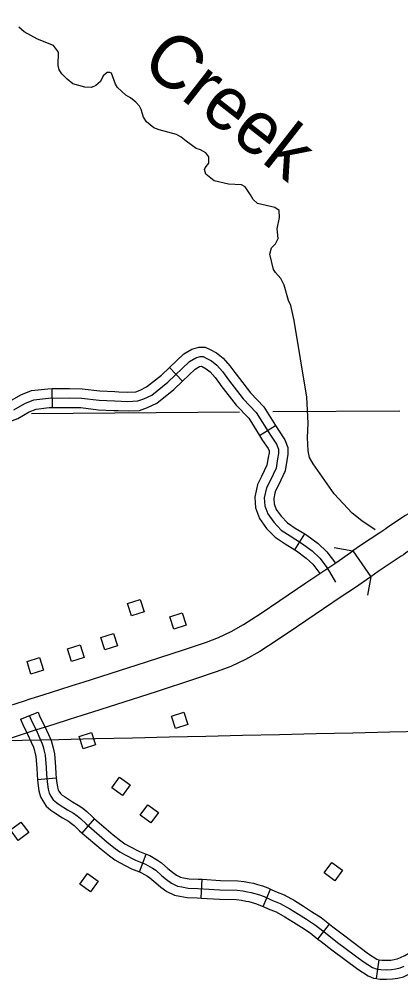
# Model space of a CAD drawing. Extents: x -19 to 366, y -4 to 359.
# Drawn here: x 128.531 to 129.107, y 199.218 to 200.67 of the extents above; entities that cross this region are included whole.
import ezdxf

# ---------------------------------------------------------------- set-up
doc = ezdxf.new("R2010")
doc.units = 0
for name, color, linetype in [('Level 10', 7, 'Continuous'), ('Level 32', 7, 'Continuous'), ('Level 35', 7, 'Continuous'), ('Level 37', 7, 'Continuous'), ('Level 45', 7, 'Continuous'), ('Level 5', 7, 'Continuous'), ('Level 56', 7, 'Continuous'), ('Level 60', 7, 'Continuous')]:
    doc.layers.add(name, color=color, linetype=linetype)

msp = doc.modelspace()

# ---------------------------------------------------------------- linework, layer by layer
at = {"layer": 'Level 10'}
msp.add_line((129.0347, 199.8689), (129.0618, 199.8301), dxfattribs=at)
for points in [[(129.1175, 199.9246), (129.1141, 199.9223), (129.0877, 199.9047), (129.0845, 199.9025), (129.0814, 199.9005), (129.0784, 199.8984), (129.0753, 199.8963), (129.0463, 199.8771), (129.0347, 199.8689)], [(129.1442, 199.8855), (129.1405, 199.883), (129.1141, 199.8654), (129.111, 199.8633), (129.1078, 199.8612), (129.1046, 199.859), (129.1015, 199.8569), (129.073, 199.8379), (129.0618, 199.8301)], [(128.5393, 199.6433), (128.548, 199.6461), (128.569, 199.6526), (128.5924, 199.6601), (128.6113, 199.6662), (128.6278, 199.6714), (128.7236, 199.702), (128.7808, 199.7206), (128.8139, 199.7317), (128.8319, 199.7386), (128.8509, 199.7474), (128.8695, 199.7581), (128.8949, 199.7743), (128.9247, 199.7942), (128.9639, 199.8209), (128.9909, 199.8389), (129.0103, 199.8519), (129.0347, 199.8689)], [(129.0618, 199.8301), (129.037, 199.8128), (129.0172, 199.7996), (128.9904, 199.7816), (128.9512, 199.7549), (128.9207, 199.7346), (128.8941, 199.7177), (128.8728, 199.7053), (128.8504, 199.695), (128.8299, 199.6871), (128.7956, 199.6756), (128.7381, 199.6569), (128.642, 199.6262), (128.6256, 199.6211), (128.6069, 199.6151), (128.5833, 199.6075), (128.5623, 199.6009), (128.554, 199.5982)], [(128.5046, 199.6319), (128.5393, 199.6433)], [(128.554, 199.5982), (128.5192, 199.5869)]]:
    msp.add_lwpolyline(points, dxfattribs=at)
at = {"layer": 'Level 32'}
for p, q in [((128.5334, 199.6156), (128.5599, 199.6259)), ((128.5588, 199.5244), (128.5871, 199.5269)), ((128.6265, 199.444), (128.6451, 199.4655)), ((128.7126, 199.3854), (128.7228, 199.412)), ((128.8058, 199.3459), (128.8074, 199.3743)), ((128.8993, 199.3333), (128.9105, 199.3594)), ((128.982, 199.2843), (128.9993, 199.3069)), ((129.0704, 199.2248), (129.0744, 199.2529))]:
    msp.add_line(p, q, dxfattribs=at)
for points in [[(128.5466, 199.6207), (128.5496, 199.6132), (128.5567, 199.5993), (128.5625, 199.5865), (128.566, 199.5783), (128.5675, 199.5738), (128.5687, 199.5691), (128.5704, 199.5613), (128.5721, 199.5427), (128.5724, 199.5324), (128.5734, 199.5209), (128.575, 199.5103), (128.5767, 199.5038), (128.579, 199.4996), (128.5827, 199.494), (128.5876, 199.4898), (128.5915, 199.4871), (128.6041, 199.479), (128.6131, 199.4737), (128.6188, 199.47), (128.6238, 199.4659), (128.6321, 199.4579), (128.6639, 199.4304), (128.6759, 199.4208), (128.683, 199.4158), (128.6904, 199.4116), (128.7067, 199.4029), (128.7221, 199.397), (128.7323, 199.3911), (128.7372, 199.3878), (128.7465, 199.3797), (128.7536, 199.3738), (128.7612, 199.3682), (128.7703, 199.3641), (128.7765, 199.3627), (128.7861, 199.3611), (128.8006, 199.3604), (128.8342, 199.3585), (128.8603, 199.3578), (128.8685, 199.3567), (128.8758, 199.3555), (128.8814, 199.3545), (128.8869, 199.3528), (128.8936, 199.3509), (128.9009, 199.3481), (128.9125, 199.343), (128.9251, 199.3379), (128.9394, 199.33), (128.9527, 199.3216), (128.9648, 199.314), (128.9784, 199.305), (128.9958, 199.2916), (129.0117, 199.2792), (129.0504, 199.2504), (129.0644, 199.2415), (129.0697, 199.2392), (129.0771, 199.2382), (129.0854, 199.2381), (129.0932, 199.2383), (129.0997, 199.2392), (129.1063, 199.2408), (129.1123, 199.2436)], [(128.5599, 199.6259), (128.5625, 199.619), (128.5695, 199.6055), (128.5755, 199.5922), (128.5793, 199.5833), (128.5811, 199.5777), (128.5825, 199.5724), (128.5845, 199.5635), (128.5863, 199.5435), (128.5866, 199.5332), (128.5871, 199.5269)], [(128.5334, 199.6156), (128.5366, 199.6074), (128.5439, 199.5931), (128.5495, 199.5807), (128.5527, 199.5733), (128.5538, 199.5699), (128.5549, 199.5657), (128.5564, 199.5591), (128.5579, 199.5418), (128.5582, 199.5315), (128.5588, 199.5244)], [(128.5588, 199.5244), (128.5593, 199.5192), (128.5611, 199.5074), (128.5634, 199.4986), (128.5668, 199.4923), (128.5719, 199.4845), (128.5789, 199.4786), (128.5836, 199.4753), (128.5967, 199.4669), (128.6056, 199.4616), (128.6104, 199.4585), (128.6143, 199.4553), (128.6225, 199.4474), (128.6265, 199.444)], [(128.5871, 199.5269), (128.5875, 199.5226), (128.589, 199.5132), (128.59, 199.5091), (128.5912, 199.5068), (128.5934, 199.5035), (128.5962, 199.5011), (128.5994, 199.4989), (128.6116, 199.4911), (128.6205, 199.4858), (128.6272, 199.4815), (128.6332, 199.4765), (128.6417, 199.4684), (128.6451, 199.4655)], [(128.6451, 199.4655), (128.673, 199.4413), (128.6845, 199.4321), (128.6906, 199.4278), (128.6972, 199.4241), (128.7126, 199.4159), (128.7228, 199.412)], [(128.6265, 199.444), (128.6548, 199.4195), (128.6674, 199.4094), (128.6754, 199.4038), (128.6836, 199.3992), (128.7008, 199.39), (128.7126, 199.3854)], [(128.7228, 199.412), (128.7282, 199.4099), (128.7398, 199.4032), (128.7459, 199.3991), (128.7557, 199.3906), (128.7624, 199.385), (128.7685, 199.3805), (128.7749, 199.3776), (128.7792, 199.3766), (128.7876, 199.3752), (128.8013, 199.3746), (128.8074, 199.3743)], [(128.7126, 199.3854), (128.7159, 199.3842), (128.7247, 199.379), (128.7286, 199.3765), (128.7373, 199.3689), (128.7449, 199.3626), (128.754, 199.3559), (128.7657, 199.3506), (128.7737, 199.3487), (128.7847, 199.3469), (128.7999, 199.3463), (128.8058, 199.3459)], [(128.8074, 199.3743), (128.8349, 199.3727), (128.8614, 199.372), (128.8706, 199.3708), (128.8782, 199.3695), (128.8848, 199.3684), (128.8909, 199.3664), (128.8982, 199.3644), (128.9063, 199.3612), (128.9105, 199.3594)], [(128.9105, 199.3594), (128.918, 199.3561), (128.9312, 199.3507), (128.9467, 199.3422), (128.9603, 199.3336), (128.9725, 199.3259), (128.9867, 199.3166), (128.9993, 199.3069)], [(128.8058, 199.3459), (128.8336, 199.3443), (128.8592, 199.3436), (128.8665, 199.3427), (128.8734, 199.3415), (128.878, 199.3407), (128.8828, 199.3392), (128.8891, 199.3374), (128.8955, 199.3349), (128.8993, 199.3333)], [(128.8993, 199.3333), (128.907, 199.3299), (128.919, 199.3251), (128.9322, 199.3178), (128.9451, 199.3096), (128.9571, 199.302), (128.9702, 199.2934), (128.982, 199.2843)], [(128.9993, 199.3069), (129.0045, 199.3028), (129.0204, 199.2904), (129.0584, 199.2621), (129.071, 199.2541), (129.0736, 199.253), (129.0744, 199.2529)], [(128.982, 199.2843), (128.9871, 199.2804), (129.0031, 199.2679), (129.0423, 199.2387), (129.0577, 199.229), (129.0658, 199.2254), (129.0704, 199.2248)], [(129.0744, 199.2529), (129.0782, 199.2524), (129.0853, 199.2523), (129.092, 199.2525), (129.0971, 199.2532), (129.1016, 199.2543), (129.1064, 199.2565), (129.1131, 199.2596), (129.1225, 199.2648), (129.1361, 199.2758), (129.1441, 199.2828), (129.149, 199.2853), (129.154, 199.2874), (129.1569, 199.2885)], [(129.0704, 199.2248), (129.076, 199.224), (129.0856, 199.2239), (129.0944, 199.2241), (129.1024, 199.2252), (129.111, 199.2274), (129.1182, 199.2307), (129.1259, 199.2342), (129.1384, 199.2411), (129.1543, 199.254), (129.1602, 199.2591), (129.1611, 199.2596), (129.1645, 199.261), (129.1668, 199.2619)]]:
    msp.add_lwpolyline(points, dxfattribs=at)
at = {"layer": 'Level 35'}
for points in [[(128.931, 200.2695), (128.926, 200.2793), (128.9179, 200.2883), (128.9148, 200.2932), (128.9095, 200.3162), (128.912, 200.3254), (128.918, 200.3319), (128.922, 200.3399), (128.9207, 200.3543), (128.9242, 200.3714), (128.9233, 200.3817), (128.9168, 200.3865), (128.8909, 200.3922), (128.8844, 200.3986), (128.8805, 200.4057), (128.8724, 200.4174), (128.8667, 200.4203), (128.8469, 200.4216), (128.8257, 200.4266), (128.8127, 200.4366), (128.811, 200.4435), (128.8117, 200.4461), (128.8173, 200.453), (128.8172, 200.4625), (128.8129, 200.4689), (128.8049, 200.4733), (128.7984, 200.4751), (128.7831, 200.4863), (128.7758, 200.4923), (128.7686, 200.4963), (128.7424, 200.5032), (128.7344, 200.5065), (128.7233, 200.5154), (128.7186, 200.5226), (128.7154, 200.5339), (128.7127, 200.5392), (128.7073, 200.5452), (128.6992, 200.5515), (128.692, 200.5556), (128.6797, 200.5672), (128.6766, 200.5721), (128.6707, 200.5887), (128.668, 200.5898), (128.6642, 200.5897), (128.6582, 200.5847), (128.6538, 200.5763), (128.6467, 200.5701), (128.6403, 200.5674), (128.6301, 200.5676), (128.6122, 200.5727), (128.6038, 200.5798), (128.5957, 200.5876), (128.5915, 200.594), (128.5899, 200.6001), (128.5907, 200.6202), (128.583, 200.6307), (128.559, 200.6398), (128.5387, 200.6513), (128.5307, 200.658)], [(129.0682, 199.9009), (129.0481, 199.9145), (129.0339, 199.9261), (129.0066, 199.9549), (128.9749, 200), (128.9691, 200.0098), (128.9674, 200.0196), (128.9663, 200.0397), (128.9671, 200.0617), (128.9654, 200.1004), (128.9462, 200.2162), (128.941, 200.2389), (128.9374, 200.2464), (128.931, 200.2695)]]:
    msp.add_lwpolyline(points, dxfattribs=at)
at = {"layer": 'Level 37'}
for points in [[(129.0067, 199.8739), (129.0347, 199.8689)], [(129.0618, 199.8301), (129.0568, 199.8022)]]:
    msp.add_lwpolyline(points, dxfattribs=at)
at = {"layer": 'Level 45'}
for p, q in [((128.7776, 200.1247), (128.758, 200.1452)), ((128.5816, 200.0851), (128.5812, 200.1135)), ((128.894, 200.0428), (128.918, 200.058)), ((128.9471, 199.8704), (128.9621, 199.8945))]:
    msp.add_line(p, q, dxfattribs=at)
for points in [[(128.758, 200.1452), (128.7796, 200.1659), (128.792, 200.1731), (128.8021, 200.1759), (128.8119, 200.1759), (128.8196, 200.1723), (128.8292, 200.1675), (128.8392, 200.1593), (128.8491, 200.1481), (128.8566, 200.1376)], [(128.5233, 200.0815), (128.5399, 200.0913), (128.5536, 200.0967), (128.5756, 200.0992), (128.607, 200.0996), (128.6254, 200.0992), (128.6518, 200.0959), (128.6749, 200.0949), (128.6954, 200.0941), (128.7102, 200.0949), (128.7193, 200.0981), (128.7312, 200.1039), (128.7553, 200.123), (128.7882, 200.1544), (128.7976, 200.1599), (128.8041, 200.1617), (128.8088, 200.1617), (128.8135, 200.1595), (128.8214, 200.1555), (128.8293, 200.149), (128.838, 200.1393), (128.847, 200.1266), (128.8694, 200.0981), (128.8889, 200.0775), (128.9105, 200.0432), (128.9196, 200.0299), (128.9224, 200.0223), (128.9224, 200.0158), (128.921, 200.0075), (128.9188, 199.9937), (128.9098, 199.9746), (128.9044, 199.9641), (128.9011, 199.9489), (128.9018, 199.937), (128.9065, 199.9247), (128.9156, 199.9121)], [(128.6817, 200.1088), (128.6953, 200.1084), (128.7074, 200.1089), (128.7137, 200.1112), (128.7236, 200.116), (128.746, 200.1338), (128.758, 200.1452)], [(128.7776, 200.1247), (128.7968, 200.143), (128.8031, 200.1467), (128.8058, 200.1474), (128.8073, 200.1467), (128.8136, 200.1435), (128.8195, 200.1388), (128.8269, 200.1304), (128.8335, 200.1211)], [(128.8566, 200.1376), (128.8584, 200.1352), (128.8802, 200.1074), (128.9002, 200.0863), (128.918, 200.058)], [(128.4832, 200.0828), (128.4985, 200.0874), (128.5171, 200.0944), (128.5336, 200.1041), (128.5501, 200.1106), (128.5747, 200.1134), (128.5812, 200.1135)], [(128.5812, 200.1135), (128.6071, 200.1138), (128.6264, 200.1134), (128.653, 200.1101), (128.6754, 200.1091), (128.6817, 200.1088)], [(128.6807, 200.0804), (128.6955, 200.0799), (128.713, 200.0808), (128.7248, 200.085), (128.7388, 200.0918), (128.7647, 200.1123), (128.7776, 200.1247)], [(128.8335, 200.1211), (128.8356, 200.1181), (128.8586, 200.0888), (128.8776, 200.0688), (128.894, 200.0428)], [(128.4914, 200.0556), (128.5076, 200.0604), (128.5294, 200.0686), (128.5461, 200.0784), (128.5571, 200.0828), (128.5765, 200.085), (128.5816, 200.0851)], [(128.5816, 200.0851), (128.6069, 200.0853), (128.6244, 200.085), (128.6506, 200.0818), (128.6743, 200.0807), (128.6807, 200.0804)], [(128.918, 200.058), (128.9224, 200.051), (128.9323, 200.0364), (128.9367, 200.0249), (128.9367, 200.0146), (128.935, 200.0051), (128.9326, 199.9895), (128.9226, 199.9683), (128.9179, 199.9593), (128.9171, 199.9558)], [(128.894, 200.0428), (128.8986, 200.0355), (128.9069, 200.0233), (128.9082, 200.0197), (128.9082, 200.017), (128.907, 200.0098), (128.9051, 199.998), (128.8971, 199.9809), (128.8909, 199.9689), (128.8893, 199.9618)], [(128.8893, 199.9618), (128.8868, 199.95), (128.8878, 199.934), (128.8939, 199.918), (128.9046, 199.903), (128.9176, 199.8896), (128.9324, 199.8796), (128.9471, 199.8704)], [(128.9171, 199.9558), (128.9154, 199.9479), (128.9159, 199.94), (128.9192, 199.9315), (128.9265, 199.9212), (128.9359, 199.9115), (128.9478, 199.9034), (128.9621, 199.8945)], [(128.9156, 199.9121), (128.9267, 199.9005), (128.9401, 199.8915), (128.9574, 199.8807), (128.9733, 199.8691), (128.9849, 199.8583), (128.996, 199.8435), (129.0083, 199.8221)], [(128.9621, 199.8945), (128.9654, 199.8925), (128.9824, 199.8801), (128.9955, 199.8678), (129.0084, 199.8507)], [(128.9471, 199.8704), (128.9495, 199.8689), (128.9642, 199.8582), (128.9743, 199.8488), (128.9848, 199.8348)]]:
    msp.add_lwpolyline(points, dxfattribs=at)
at = {"layer": 'Level 5'}
for points in [[(128.55, 200.0761), (128.8638, 200.0784)], [(128.9139, 200.0788), (129.1058, 200.0803)]]:
    msp.add_lwpolyline(points, dxfattribs=at)
at = {"layer": 'Level 56'}
for points in [[(128.7009, 199.7713), (128.6949, 199.79), (128.7137, 199.796), (128.7197, 199.7773)], [(128.7644, 199.7511), (128.7584, 199.7699), (128.7772, 199.7759), (128.7832, 199.7571)], [(128.6607, 199.72), (128.6547, 199.7388), (128.6735, 199.7448), (128.6795, 199.726)], [(128.6103, 199.7025), (128.6044, 199.7213), (128.6232, 199.7273), (128.6292, 199.7085)], [(128.549, 199.6834), (128.5431, 199.7022), (128.5619, 199.7082), (128.5679, 199.6894)], [(128.7669, 199.6014), (128.761, 199.6202), (128.7798, 199.6262), (128.7858, 199.6074)], [(128.6278, 199.5707), (128.6218, 199.5895), (128.6406, 199.5955), (128.6466, 199.5767)], [(128.6988, 199.5164), (128.6872, 199.5005), (128.6712, 199.512), (128.6828, 199.528)], [(128.7415, 199.4751), (128.73, 199.4592), (128.714, 199.4707), (128.7255, 199.4867)], [(128.5456, 199.4446), (128.5297, 199.4329), (128.518, 199.4488), (128.5338, 199.4605)], [(129.0191, 199.3882), (129.0075, 199.3722), (128.9915, 199.3838), (129.0031, 199.3997)], [(128.6505, 199.3712), (128.639, 199.3552), (128.623, 199.3668), (128.6345, 199.3828)]]:
    msp.add_lwpolyline(points, close=True, dxfattribs=at)
at = {"layer": 'Level 60'}
for points in [[(132.1027, 1.3746), (131.9232, 9.99), (131.7429, 18.6056), (131.5621, 27.2214), (131.3806, 35.8373), (131.1985, 44.4533), (131.0158, 53.0695), (130.8324, 61.6859), (130.6485, 70.3024), (130.4639, 78.919), (130.2786, 87.5358), (130.0928, 96.1527), (129.9063, 104.7698), (129.7193, 113.387), (129.5316, 122.0044), (129.3433, 130.6219), (129.1543, 139.2396), (128.9648, 147.8575), (128.7746, 156.4754), (128.5838, 165.0936), (128.3925, 173.7119), (128.2005, 182.3303), (128.0078, 190.9489), (127.8146, 199.5676), (127.6208, 208.1865), (127.4264, 216.8056), (127.2313, 225.4247), (127.0357, 234.0441), (126.8394, 242.6636), (126.6425, 251.2833), (126.4451, 259.9031), (126.247, 268.523), (126.0483, 277.1431), (125.849, 285.7634), (125.6492, 294.3838), (125.4487, 303.0044), (125.2476, 311.6252), (125.0459, 320.2461), (124.8437, 328.8671), (124.6408, 337.4883), (124.4373, 346.1097)], [(0, 198.1326), (7.1014, 198.137), (14.2028, 198.1503), (21.3042, 198.1724), (28.4055, 198.2034), (35.5068, 198.2433), (42.6081, 198.292), (49.7092, 198.3496), (56.8103, 198.4161), (63.9113, 198.4913), (71.0123, 198.5755), (78.1131, 198.6685), (85.2137, 198.7704), (92.3143, 198.8811), (99.4147, 199.0007), (106.5149, 199.1291), (113.615, 199.2664), (120.7149, 199.4126), (127.8146, 199.5676), (134.9141, 199.7315), (142.0135, 199.9042), (149.1125, 200.0858), (156.2114, 200.2762), (163.31, 200.4755), (170.4084, 200.6837), (177.5065, 200.9007), (184.6043, 201.1265), (191.7018, 201.3612), (198.799, 201.6048), (205.896, 201.8572), (212.9926, 202.1185), (220.0888, 202.3886), (227.1848, 202.6676), (234.2803, 202.9554), (241.3755, 203.2521), (248.4704, 203.5576), (255.5648, 203.872), (262.6589, 204.1952), (269.7525, 204.5273), (276.8457, 204.8682), (283.9385, 205.218), (291.0309, 205.5766), (298.1228, 205.9441), (305.2142, 206.3204), (312.3051, 206.7056), (319.3956, 207.0996), (326.4856, 207.5024), (333.5751, 207.9141), (340.664, 208.3347)], [(0, 189.5162), (7.1121, 189.5206), (14.2243, 189.5339), (21.3364, 189.556), (28.4484, 189.5869), (35.5605, 189.6267), (42.6725, 189.6754), (49.7844, 189.7329), (56.8962, 189.7992), (64.0079, 189.8744), (71.1196, 189.9584), (78.2311, 190.0512), (85.3425, 190.1529), (92.4538, 190.2635), (99.5649, 190.3829), (106.6759, 190.5111), (113.7867, 190.6482), (120.8974, 190.7941), (128.0078, 190.9489), (135.1181, 191.1125), (142.2282, 191.2849), (149.338, 191.4662), (156.4476, 191.6563), (163.5569, 191.8553), (170.666, 192.0631), (177.7749, 192.2798), (184.8835, 192.5053), (191.9917, 192.7396), (199.0997, 192.9828), (206.2074, 193.2348), (213.3147, 193.4956), (220.4218, 193.7653), (227.5285, 194.0438), (234.6348, 194.3312), (241.7408, 194.6274), (248.8464, 194.9324), (255.9516, 195.2463), (263.0564, 195.569), (270.1608, 195.9005), (277.2648, 196.2409), (284.3683, 196.5901), (291.4715, 196.9481), (298.5741, 197.315), (305.6763, 197.6907), (312.7781, 198.0753), (319.8793, 198.4686), (326.9801, 198.8708), (334.0804, 199.2818), (341.1801, 199.7017)]]:
    msp.add_spline(points, degree=3, dxfattribs=at)

# ---------------------------------------------------------------- texts
at = {"layer": 'Level 35'}
msp.add_text('Creek', height=0.08, rotation=321.9868, dxfattribs=at).set_placement((128.7123, 200.5986))

doc.saveas('drawing.dxf')
